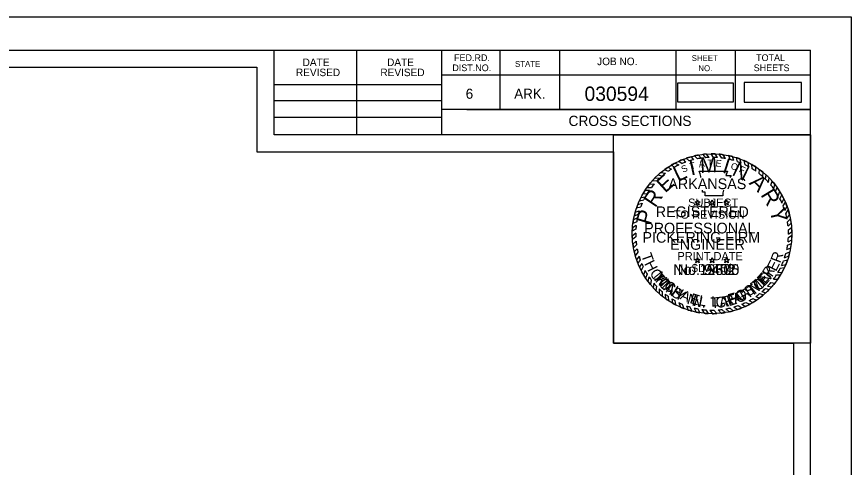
# Model space of a CAD drawing. Extents: x 1368713 to 1370673, y 380279 to 380950.
# Drawn here: x 1370575.1 to 1370672.6, y 380471.2 to 380523.8 of the extents above; entities that cross this region are included whole.
import ezdxf

# ---------------------------------------------------------------- set-up
doc = ezdxf.new("R2010")
doc.units = 0
for name, color, linetype in [('R_Border', 7, 'Continuous'), ('R_Border Notes', 7, 'Continuous'), ('R_No Plot', 7, 'Continuous'), ('R_Water', 7, 'Continuous'), ('STAMP_PE_CRAFTON', 7, 'Continuous'), ('STAMP_PE_FOSTER', 7, 'Continuous'), ('STAMP_PE_SEAL-INFO', 7, 'Continuous'), ('STAMP_PE_TAEGTMEYER', 7, 'Continuous'), ('STAMP_PE_TXT', 7, 'Continuous'), ('STAMP_PRELIMINARY', 7, 'Continuous')]:
    doc.layers.add(name, color=color, linetype=linetype)

msp = doc.modelspace()

# ---------------------------------------------------------------- linework, layer by layer
at = {"layer": 'R_Border'}
for p, q in [((1370351.629, 380519.876), (1370667.809, 380519.876)), ((1370605.169, 380509.996), (1370605.169, 380519.876)), ((1370614.849, 380509.996), (1370614.849, 380519.876)), ((1370624.709, 380519.876), (1370624.709, 380509.996)), ((1370631.549, 380519.876), (1370631.549, 380512.936)), ((1370638.489, 380519.876), (1370638.489, 380512.936)), ((1370652.069, 380519.876), (1370652.069, 380512.936)), ((1370659.009, 380519.876), (1370659.009, 380512.936)), ((1370667.809, 380314.416), (1370667.809, 380519.876)), ((1370667.809, 380516.936), (1370624.709, 380516.936)), ((1370667.809, 380516.956), (1370667.809, 380516.956)), ((1370605.169, 380515.856), (1370624.709, 380515.856)), ((1370605.169, 380513.996), (1370624.709, 380513.996)), ((1370605.169, 380512.056), (1370624.709, 380512.056)), ((1370667.809, 380512.936), (1370624.709, 380512.936)), ((1370627.669, 380512.936), (1370667.809, 380512.936)), ((1370667.809, 380509.996), (1370605.169, 380509.996))]:
    msp.add_line(p, q, dxfattribs=at)
at = {"layer": 'R_No Plot'}
for points in [[(1370339.221, 380523.77), (1370672.561, 380523.77), (1370672.561, 380310.433), (1370339.221, 380310.433)], [(1370665.809, 380419.146), (1370353.629, 380419.146), (1370353.629, 380517.876), (1370603.169, 380517.876), (1370603.169, 380507.996), (1370620.709, 380507.996), (1370644.809, 380507.996), (1370644.809, 380485.663), (1370665.809, 380485.663)], [(1370353.629, 380517.876), (1370603.169, 380517.876), (1370603.169, 380507.996), (1370620.709, 380507.996), (1370644.809, 380507.996), (1370644.809, 380485.663), (1370665.809, 380485.663), (1370665.809, 380316.416), (1370353.629, 380316.416)], [(1370644.809, 380509.996), (1370667.809, 380509.996), (1370667.809, 380485.663), (1370644.809, 380485.663)]]:
    msp.add_lwpolyline(points, close=True, dxfattribs=at)
at = {"layer": 'R_Water'}
for points in [[(1370652.257, 380513.843), (1370658.821, 380513.843), (1370658.821, 380516.029), (1370652.257, 380516.029)], [(1370660.067, 380513.781), (1370666.751, 380513.781), (1370666.751, 380516.091), (1370660.067, 380516.091)]]:
    msp.add_lwpolyline(points, close=True, dxfattribs=at)
at = {"layer": 'STAMP_PE_SEAL-INFO'}
for p, q in [((1370652.921, 380507.123), (1370653.215, 380506.798)), ((1370653.268, 380507.251), (1370653.649, 380506.946)), ((1370653.859, 380507.433), (1370654.147, 380507.086)), ((1370654.247, 380507.53), (1370654.603, 380507.187)), ((1370654.73, 380507.626), (1370655.029, 380507.259)), ((1370655.245, 380507.7), (1370655.526, 380507.317)), ((1370655.981, 380507.346), (1370655.669, 380507.739)), ((1370656.479, 380507.35), (1370656.2, 380507.76)), ((1370656.937, 380507.33), (1370656.678, 380507.754)), ((1370657.442, 380507.279), (1370657.15, 380507.723)), ((1370657.868, 380507.214), (1370657.611, 380507.67)), ((1370658.43, 380507.096), (1370658.256, 380507.555)), ((1370658.832, 380506.987), (1370658.673, 380507.456)), ((1370659.284, 380506.841), (1370659.142, 380507.32)), ((1370659.702, 380506.681), (1370659.558, 380507.177)), ((1370651.147, 380506.201), (1370651.589, 380505.999)), ((1370651.534, 380506.445), (1370651.966, 380506.222)), ((1370651.982, 380506.696), (1370652.445, 380506.471)), ((1370652.413, 380506.908), (1370652.802, 380506.633)), ((1370660.163, 380506.475), (1370660.061, 380506.973)), ((1370660.609, 380506.246), (1370660.522, 380506.755)), ((1370660.997, 380506.019), (1370660.957, 380506.52)), ((1370661.431, 380505.733), (1370661.4, 380506.248)), ((1370650.006, 380505.307), (1370650.465, 380505.169)), ((1370650.35, 380505.608), (1370650.879, 380505.507)), ((1370650.727, 380505.935), (1370651.182, 380505.73)), ((1370654.782, 380505.73), (1370658.126, 380505.73)), ((1370654.903, 380505.422), (1370654.782, 380505.73)), ((1370655.007, 380505.124), (1370654.903, 380505.422)), ((1370658.126, 380505.73), (1370657.901, 380505.238)), ((1370657.901, 380505.238), (1370658.534, 380505.238)), ((1370658.534, 380505.238), (1370658.389, 380505.01)), ((1370661.792, 380505.466), (1370661.826, 380505.953)), ((1370662.238, 380505.094), (1370662.258, 380505.616)), ((1370662.551, 380504.801), (1370662.62, 380505.3)), ((1370649.002, 380504.228), (1370649.551, 380504.251)), ((1370649.348, 380504.64), (1370649.87, 380504.601)), ((1370649.671, 380504.984), (1370650.215, 380504.943)), ((1370655.014, 380505.01), (1370655.007, 380505.124)), ((1370662.91, 380504.428), (1370662.977, 380504.954)), ((1370663.184, 380504.112), (1370663.32, 380504.583)), ((1370663.508, 380503.694), (1370663.643, 380504.194)), ((1370648.49, 380503.515), (1370649.006, 380503.548)), ((1370648.724, 380503.859), (1370649.229, 380503.854)), ((1370655.206, 380503.301), (1370655.179, 380503.519)), ((1370655.52, 380503.301), (1370655.206, 380503.301)), ((1370655.52, 380502.871), (1370655.52, 380503.301)), ((1370657.565, 380503.209), (1370657.55, 380502.871)), ((1370657.643, 380503.519), (1370657.565, 380503.209)), ((1370663.728, 380503.379), (1370663.905, 380503.843)), ((1370664.036, 380502.882), (1370664.218, 380503.373)), ((1370647.824, 380502.301), (1370648.327, 380502.405)), ((1370648.012, 380502.69), (1370648.511, 380502.755)), ((1370648.244, 380503.114), (1370648.733, 380503.134)), ((1370657.55, 380502.871), (1370655.52, 380502.871)), ((1370664.235, 380502.515), (1370664.462, 380502.96)), ((1370664.466, 380502.031), (1370664.693, 380502.516)), ((1370647.49, 380501.463), (1370647.975, 380501.599)), ((1370647.641, 380501.869), (1370648.145, 380502.015)), ((1370664.607, 380501.694), (1370664.87, 380502.128)), ((1370664.801, 380501.145), (1370665.072, 380501.62)), ((1370647.593, 380500.306), (1370647.128, 380500.057)), ((1370647.229, 380500.552), (1370647.699, 380500.745)), ((1370647.334, 380500.96), (1370647.811, 380501.128)), ((1370664.909, 380500.781), (1370665.203, 380501.233)), ((1370665.042, 380500.222), (1370665.361, 380500.669)), ((1370647.449, 380499.412), (1370647.012, 380499.131)), ((1370647.508, 380499.847), (1370647.062, 380499.625)), ((1370665.111, 380499.842), (1370665.465, 380500.195)), ((1370665.177, 380499.333), (1370665.55, 380499.669)), ((1370647.412, 380498.986), (1370646.991, 380498.73)), ((1370647.396, 380498.493), (1370646.991, 380498.158)), ((1370665.21, 380498.915), (1370665.6, 380499.206)), ((1370665.222, 380498.397), (1370665.627, 380498.718)), ((1370647.402, 380498.086), (1370647.011, 380497.761)), ((1370647.436, 380497.591), (1370647.064, 380497.234)), ((1370665.171, 380497.485), (1370665.606, 380497.742)), ((1370665.211, 380497.991), (1370665.63, 380498.268)), ((1370647.487, 380497.162), (1370647.133, 380496.788)), ((1370647.566, 380496.703), (1370647.227, 380496.335)), ((1370665.03, 380496.597), (1370665.485, 380496.792)), ((1370665.121, 380497.097), (1370665.564, 380497.316)), ((1370647.66, 380496.284), (1370647.347, 380495.869)), ((1370647.783, 380495.837), (1370647.489, 380495.419)), ((1370647.924, 380495.414), (1370647.643, 380495.002)), ((1370664.641, 380495.271), (1370665.123, 380495.402)), ((1370664.775, 380495.651), (1370665.266, 380495.852)), ((1370664.922, 380496.145), (1370665.394, 380496.347)), ((1370648.091, 380494.987), (1370647.829, 380494.565)), ((1370648.262, 380494.604), (1370648.035, 380494.143)), ((1370664.266, 380494.42), (1370664.754, 380494.488)), ((1370664.427, 380494.757), (1370664.915, 380494.853)), ((1370648.497, 380494.146), (1370648.306, 380493.656)), ((1370648.733, 380493.742), (1370648.549, 380493.271)), ((1370663.822, 380493.641), (1370664.299, 380493.635)), ((1370663.993, 380493.922), (1370664.494, 380493.976)), ((1370648.935, 380493.43), (1370648.826, 380492.878)), ((1370649.216, 380493.04), (1370649.114, 380492.509)), ((1370649.52, 380492.662), (1370649.433, 380492.142)), ((1370663.174, 380492.753), (1370663.636, 380492.674)), ((1370663.482, 380493.147), (1370663.987, 380493.15)), ((1370649.823, 380492.325), (1370649.761, 380491.802)), ((1370650.145, 380491.999), (1370650.115, 380491.47)), ((1370650.49, 380491.687), (1370650.486, 380491.158)), ((1370662.13, 380491.688), (1370662.602, 380491.559)), ((1370662.536, 380492.061), (1370662.977, 380491.923)), ((1370662.791, 380492.32), (1370663.268, 380492.235)), ((1370650.849, 380491.392), (1370650.868, 380490.868)), ((1370651.188, 380491.143), (1370651.224, 380490.624)), ((1370651.615, 380490.861), (1370651.676, 380490.348)), ((1370651.965, 380490.655), (1370652.056, 380490.142)), ((1370660.641, 380490.648), (1370661.058, 380490.416)), ((1370661.055, 380490.893), (1370661.505, 380490.698)), ((1370661.399, 380491.121), (1370661.838, 380490.932)), ((1370661.86, 380491.464), (1370662.327, 380491.318)), ((1370652.446, 380490.405), (1370652.603, 380489.884)), ((1370652.819, 380490.236), (1370652.992, 380489.726)), ((1370653.311, 380490.044), (1370653.521, 380489.542)), ((1370653.721, 380489.909), (1370653.947, 380489.42)), ((1370654.229, 380489.771), (1370654.441, 380489.305)), ((1370654.626, 380489.685), (1370654.873, 380489.227)), ((1370655.127, 380489.603), (1370655.367, 380489.163)), ((1370655.563, 380489.556), (1370655.837, 380489.127)), ((1370657.465, 380489.6), (1370657.837, 380489.242)), ((1370657.91, 380489.67), (1370658.298, 380489.33)), ((1370658.402, 380489.774), (1370658.78, 380489.449)), ((1370658.862, 380489.898), (1370659.278, 380489.601)), ((1370659.354, 380490.061), (1370659.797, 380489.793)), ((1370659.774, 380490.226), (1370660.197, 380489.965)), ((1370660.233, 380490.435), (1370660.717, 380490.223)), ((1370656.048, 380489.529), (1370656.35, 380489.116)), ((1370656.508, 380489.527), (1370656.851, 380489.131)), ((1370657.026, 380489.554), (1370657.352, 380489.174))]:
    msp.add_line(p, q, dxfattribs=at)
for radius, start, end in [(9.323, 111.31242, 114.70259), (9.323, 105.23389, 109.03519), (9.323, 99.75254, 102.77648), (8.914, 98.25799, 101.03289), (9.323, 93.93815, 96.55172), (8.914, 92.11016, 95.03666), (9.323, 87.72979, 90.67067), (8.914, 85.96279, 88.9097), (9.323, 81.97315, 84.82355), (8.914, 79.92642, 82.69597), (9.323, 75.31251, 77.94263), (8.914, 73.55748, 76.23144), (9.323, 69.60611, 72.30577), (9.323, 123.61993, 126.59063), (9.323, 117.65441, 120.80988), (8.914, 115.68692, 119.15827), (8.914, 110.30864, 113.16588), (8.914, 104.03521, 107.36155), (8.914, 67.62483, 70.50398), (9.323, 63.13288, 66.2704), (8.914, 61.15575, 64.37837), (9.323, 56.90029, 60.09423), (9.323, 129.73259, 132.53764), (8.914, 127.52969, 130.96829), (8.914, 121.97456, 125.11001), (8.914, 54.92383, 58.27016), (8.914, 48.30163, 52.03953), (9.323, 50.3492, 53.71593), (9.323, 44.3405, 47.39292), (9.323, 141.60556, 144.44865), (8.914, 139.30101, 142.58729), (9.323, 135.40208, 138.30314), (8.914, 133.13306, 136.25623), (8.914, 42.22116, 45.55119), (9.323, 38.12472, 41.23157), (9.323, 147.00719, 149.89904), (8.914, 145.01972, 148.21036), (8.914, 36.13503, 39.53106), (8.914, 29.90321, 33.66454), (9.323, 31.96138, 35.42937), (9.323, 152.86398, 155.51889), (8.914, 151.03153, 153.57304), (8.914, 23.77322, 27.22114), (9.323, 25.93909, 29.01247), (9.323, 158.40766, 161.07015), (8.914, 156.34018, 159.23194), (8.914, 17.68022, 21.42509), (9.323, 19.95381, 23.31409), (9.323, 164.3068, 166.89395), (8.914, 167.90481, 170.90393), (8.914, 162.43309, 165.00133), (8.914, 11.54445, 15.23639), (9.323, 13.84205, 17.44468), (9.323, 170.0003, 172.68778), (8.914, 173.73, 176.47337), (8.914, 5.7599, 9.06056), (9.323, 7.58519, 10.86211), (9.323, 175.74093, 178.2066), (8.914, 179.64537, 182.26333), (8.914, 359.73289, 3.06392), (9.323, 1.72155, 4.72681), (9.323, 181.72508, 184.16255), (8.914, 185.45389, 188.23401), (8.914, 353.86319, 357.12742), (9.323, 355.71562, 358.95694), (9.323, 187.42037, 190.19271), (8.914, 191.22736, 193.98583), (8.914, 348.07782, 351.34355), (9.323, 349.83047, 353.08845), (9.323, 193.03695, 195.99732), (9.323, 198.89671, 201.62812), (8.914, 196.96751, 199.83526), (8.914, 341.77699, 345.09248), (9.323, 337.38367, 340.99332), (9.323, 343.89247, 347.03502), (9.323, 204.54793, 207.43282), (8.914, 202.77613, 205.47915), (8.914, 335.6038, 339.18578), (9.323, 331.40371, 334.93315), (9.323, 210.86355, 213.65709), (8.914, 208.78826, 211.79343), (8.914, 323.58513, 327.44069), (9.323, 325.44052, 328.98725), (8.914, 329.55488, 333.20757), (9.323, 216.61154, 219.49098), (8.914, 214.18375, 217.27474), (8.914, 220.39088, 223.30564), (8.914, 316.65308, 320.37109), (9.323, 318.28455, 321.80429), (9.323, 222.47995, 225.38008), (8.914, 226.24938, 229.24068), (8.914, 310.77436, 314.31605), (9.323, 312.45177, 315.66328), (9.323, 228.36648, 231.34802), (8.914, 232.22904, 234.93361), (9.323, 234.29502, 236.94517), (8.914, 238.22227, 240.83529), (8.914, 299.07679, 302.17235), (9.323, 300.62101, 303.87026), (8.914, 304.82299, 308.51428), (9.323, 306.37206, 310.20799), (9.323, 240.1977, 242.86128), (8.914, 244.32043, 246.94859), (9.323, 246.57598, 249.15579), (8.914, 250.34912, 253.12157), (8.914, 256.50505, 259.11916), (8.914, 262.37828, 265.20115), (8.914, 274.61565, 277.44863), (8.914, 280.34588, 283.58137), (8.914, 286.64233, 289.97826), (9.323, 288.57086, 291.97334), (8.914, 292.87452, 296.11851), (9.323, 294.64808, 298.21662), (9.323, 252.59667, 255.32518), (9.323, 258.44328, 261.13983), (9.323, 264.19784, 267.10092), (8.914, 268.3215, 271.27698), (9.323, 270.25484, 273.33609), (9.323, 276.42389, 279.43574), (9.323, 282.31994, 285.37019)]:
    msp.add_arc((1370656.309, 380498.438), radius, start, end, dxfattribs=at)
at = {"layer": 'STAMP_PE_TXT'}
for p, q in [((1370654.535, 380502.154), (1370654.611, 380502.387)), ((1370654.611, 380502.387), (1370654.687, 380502.154)), ((1370656.233, 380502.154), (1370656.309, 380502.387)), ((1370656.309, 380502.387), (1370656.385, 380502.154)), ((1370657.931, 380502.154), (1370658.007, 380502.387)), ((1370658.007, 380502.387), (1370658.083, 380502.154)), ((1370654.488, 380502.01), (1370654.29, 380502.154)), ((1370654.29, 380502.154), (1370654.535, 380502.154)), ((1370654.413, 380501.776), (1370654.488, 380502.01)), ((1370654.611, 380501.921), (1370654.413, 380501.776)), ((1370654.809, 380501.776), (1370654.611, 380501.921)), ((1370654.687, 380502.154), (1370654.932, 380502.154)), ((1370654.932, 380502.154), (1370654.734, 380502.01)), ((1370654.734, 380502.01), (1370654.809, 380501.776)), ((1370656.186, 380502.01), (1370655.988, 380502.154)), ((1370655.988, 380502.154), (1370656.233, 380502.154)), ((1370656.111, 380501.776), (1370656.186, 380502.01)), ((1370656.309, 380501.921), (1370656.111, 380501.776)), ((1370656.507, 380501.776), (1370656.309, 380501.921)), ((1370656.385, 380502.154), (1370656.63, 380502.154)), ((1370656.63, 380502.154), (1370656.432, 380502.01)), ((1370656.432, 380502.01), (1370656.507, 380501.776)), ((1370657.884, 380502.01), (1370657.686, 380502.154)), ((1370657.686, 380502.154), (1370657.931, 380502.154)), ((1370657.809, 380501.776), (1370657.884, 380502.01)), ((1370658.007, 380501.921), (1370657.809, 380501.776)), ((1370658.205, 380501.776), (1370658.007, 380501.921)), ((1370658.083, 380502.154), (1370658.328, 380502.154)), ((1370658.328, 380502.154), (1370658.13, 380502.01)), ((1370658.13, 380502.01), (1370658.205, 380501.776)), ((1370654.488, 380495.303), (1370654.29, 380495.447)), ((1370654.29, 380495.447), (1370654.535, 380495.447)), ((1370654.535, 380495.447), (1370654.611, 380495.68)), ((1370654.611, 380495.68), (1370654.687, 380495.447)), ((1370654.687, 380495.447), (1370654.932, 380495.447)), ((1370654.932, 380495.447), (1370654.734, 380495.303)), ((1370656.186, 380495.303), (1370655.988, 380495.447)), ((1370655.988, 380495.447), (1370656.233, 380495.447)), ((1370656.233, 380495.447), (1370656.309, 380495.68)), ((1370656.309, 380495.68), (1370656.385, 380495.447)), ((1370656.385, 380495.447), (1370656.63, 380495.447)), ((1370656.63, 380495.447), (1370656.432, 380495.303)), ((1370657.884, 380495.303), (1370657.686, 380495.447)), ((1370657.686, 380495.447), (1370657.931, 380495.447)), ((1370657.931, 380495.447), (1370658.007, 380495.68)), ((1370658.007, 380495.68), (1370658.083, 380495.447)), ((1370658.083, 380495.447), (1370658.328, 380495.447)), ((1370658.328, 380495.447), (1370658.13, 380495.303)), ((1370654.413, 380495.069), (1370654.488, 380495.303)), ((1370654.611, 380495.214), (1370654.413, 380495.069)), ((1370654.809, 380495.069), (1370654.611, 380495.214)), ((1370654.734, 380495.303), (1370654.809, 380495.069)), ((1370656.111, 380495.069), (1370656.186, 380495.303)), ((1370656.309, 380495.214), (1370656.111, 380495.069)), ((1370656.507, 380495.069), (1370656.309, 380495.214)), ((1370656.432, 380495.303), (1370656.507, 380495.069)), ((1370657.809, 380495.069), (1370657.884, 380495.303)), ((1370658.007, 380495.214), (1370657.809, 380495.069)), ((1370658.205, 380495.069), (1370658.007, 380495.214)), ((1370658.13, 380495.303), (1370658.205, 380495.069))]:
    msp.add_line(p, q, dxfattribs=at)
at = {"layer": 'STAMP_PRELIMINARY'}
msp.add_circle((1370656.309, 380498.438), 9.323, dxfattribs=at)

# ---------------------------------------------------------------- texts
at = {"layer": 'R_Border'}
for s, height, p in [('DATE', 0.8792, (1370608.507, 380518.012)), ('DATE', 0.8792, (1370618.367, 380518.012)), ('FED.RD.', 0.7819, (1370626.189, 380518.596)), ('JOB NO.', 0.8792, (1370642.889, 380518.116)), ('SHEET', 0.684, (1370653.929, 380518.596)), ('TOTAL', 0.7819, (1370661.449, 380518.596)), ('DIST.NO.', 0.7819, (1370625.989, 380517.416)), ('STATE', 0.684, (1370633.309, 380517.916)), ('NO.', 0.684, (1370654.709, 380517.416)), ('SHEETS', 0.7819, (1370661.169, 380517.416)), ('REVISED', 0.8792, (1370607.727, 380516.832)), ('REVISED', 0.8792, (1370617.587, 380516.832)), ('6', 1.172, (1370627.549, 380514.196)), ('ARK.', 1.1723, (1370633.209, 380514.196))]:
    msp.add_text(s, height=height, rotation=360, dxfattribs=at).set_placement(p)
at = {"layer": 'R_Border Notes'}
for s, height, p in [('030594', 1.68, (1370641.42, 380513.941)), ('CROSS SECTIONS', 1.2, (1370639.548, 380511.014))]:
    msp.add_text(s, height=height, rotation=360, dxfattribs=at).set_placement(p)
at = {"layer": 'STAMP_PE_CRAFTON'}
for s, rotation, p in [('No. 12370', 360, (1370651.771, 380493.635)), ('T', 310.74416, (1370649.275, 380493.336)), ('N', 49.24107, (1370662.591, 380492.46)), ('O', 317.64216, (1370649.942, 380492.525)), ('N', 324.45371, (1370650.788, 380491.74)), ('T', 34.11362, (1370660.886, 380491.077)), ('O', 41.83906, (1370661.744, 380491.679)), ('Y', 331.16864, (1370651.821, 380491.024)), ('A', 20.51248, (1370658.99, 380490.194)), ('F', 28.78207, (1370659.97, 380490.568)), ('N', 347.47515, (1370653.876, 380490.108)), ('C', 6.01169, (1370656.78, 380489.779)), ('R', 14.81888, (1370657.877, 380489.894)), ('.', 356.89262, (1370655.105, 380489.831))]:
    msp.add_text(s, height=1.25, rotation=rotation, dxfattribs=at).set_placement(p)
at = {"layer": 'STAMP_PE_FOSTER'}
for s, height, rotation, p in [('No. 9402', 1.25, 360, (1370652.295, 380493.635)), ('R', 1.2, 54.5031, (1370663.033, 380493.249)), ('M', 1.2, 308.33902, (1370649.425, 380493.46)), ('E', 1.2, 46.96131, (1370662.31, 380492.428)), ('I', 1.2, 314.18423, (1370650.223, 380492.523)), ('C', 1.2, 319.87327, (1370650.577, 380492.169)), ('T', 1.2, 39.41938, (1370661.451, 380491.678)), ('H', 1.2, 327.72349, (1370651.506, 380491.433)), ('A', 1.2, 335.72761, (1370652.487, 380490.851)), ('F', 1.2, 15.86908, (1370658.344, 380490.193)), ('O', 1.2, 23.71897, (1370659.388, 380490.521)), ('S', 1.2, 31.72336, (1370660.5, 380491.051)), ('E', 1.2, 343.5779, (1370653.624, 380490.381)), ('L', 1.2, 350.81148, (1370654.683, 380490.103)), ('L', 1.2, 1.26658, (1370656.222, 380489.947)), ('.', 1.2, 6.80354, (1370657.269, 380490.005))]:
    msp.add_text(s, height=height, rotation=rotation, dxfattribs=at).set_placement(p)
at = {"layer": 'STAMP_PE_TAEGTMEYER'}
for s, rotation, p in [('T', 289.64597, (1370648.003, 380495.948)), ('H', 296.73386, (1370648.363, 380494.964)), ('E', 63.0984, (1370663.755, 380493.971)), ('R', 69.57001, (1370664.254, 380494.953)), ('No. 19605', 360, (1370651.771, 380493.635)), ('Y', 53.99864, (1370663.086, 380493.031)), ('O', 303.77078, (1370648.956, 380493.856)), ('M', 314.20329, (1370649.611, 380492.905)), ('E', 46.80938, (1370662.347, 380492.216)), ('A', 321.0594, (1370650.573, 380491.94)), ('M', 39.30005, (1370661.307, 380491.336)), ('S', 327.82385, (1370651.399, 380491.296)), ('G', 23.30524, (1370659.309, 380490.3)), ('T', 31.46601, (1370660.409, 380490.793)), ('N', 344.27273, (1370653.296, 380490.29)), ('T', 3.00609, (1370656.173, 380489.759)), ('A', 8.98261, (1370657.22, 380489.814)), ('E', 17.68363, (1370658.259, 380489.97)), ('.', 350.64643, (1370654.508, 380489.958))]:
    msp.add_text(s, height=1.25, rotation=rotation, dxfattribs=at).set_placement(p)
at = {"layer": 'STAMP_PE_TXT'}
for s, height, rotation, p in [('T', 0.781, 1.82479, (1370655.779, 380506.296)), ('S', 0.781, 23.5541, (1370652.908, 380505.542)), ('T', 0.781, 16.311, (1370653.831, 380505.914)), ('A', 0.781, 9.0679, (1370654.793, 380506.167)), ('E', 0.781, 355.20019, (1370656.69, 380506.305)), ('O', 0.781, 342.25065, (1370658.416, 380506.028)), ('F', 0.781, 335.00755, (1370659.382, 380505.69)), ('ARKANSAS', 1.25, 360, (1370651.201, 380503.649)), ('REGISTERED', 1.25, 360, (1370649.726, 380500.379)), ('PROFESSIONAL', 1.25, 360, (1370648.377, 380498.478)), ('ENGINEER', 1.25, 360, (1370651.418, 380496.576))]:
    msp.add_text(s, height=height, rotation=rotation, dxfattribs=at).set_placement(p)
at = {"layer": 'STAMP_PRELIMINARY'}
for s, height, rotation, p in [('M', 1.8, 3.10738, (1370654.945, 380505.534)), ('I', 1.8, 342.31637, (1370657.412, 380505.601)), ('L', 1.8, 25.51305, (1370652.318, 380504.466)), ('I', 1.8, 12.52485, (1370653.847, 380505.225)), ('N', 1.8, 333.9382, (1370658.52, 380505.327)), ('E', 1.8, 42.35784, (1370650.835, 380503.135)), ('A', 1.8, 315.65789, (1370660.554, 380504.302)), ('R', 1.8, 56.22922, (1370649.68, 380501.402)), ('R', 1.8, 301.38306, (1370661.922, 380502.988)), ('SUBJECT', 0.96, 360, (1370653.509, 380501.588)), ('Y', 1.8, 283.25926, (1370663.011, 380501.201)), ('P', 1.8, 73.91301, (1370649.13, 380499.379)), ('TO REVISION', 0.96, 360, (1370651.844, 380500.203)), ('PICKERING FIRM', 1.25, 360, (1370648.182, 380497.401)), ('PRINT DATE', 0.96, 360, (1370652.266, 380495.354)), ('$DATE$', 0.96, 360, (1370653.943, 380493.969))]:
    msp.add_text(s, height=height, rotation=rotation, dxfattribs=at).set_placement(p)

doc.saveas('drawing.dxf')
